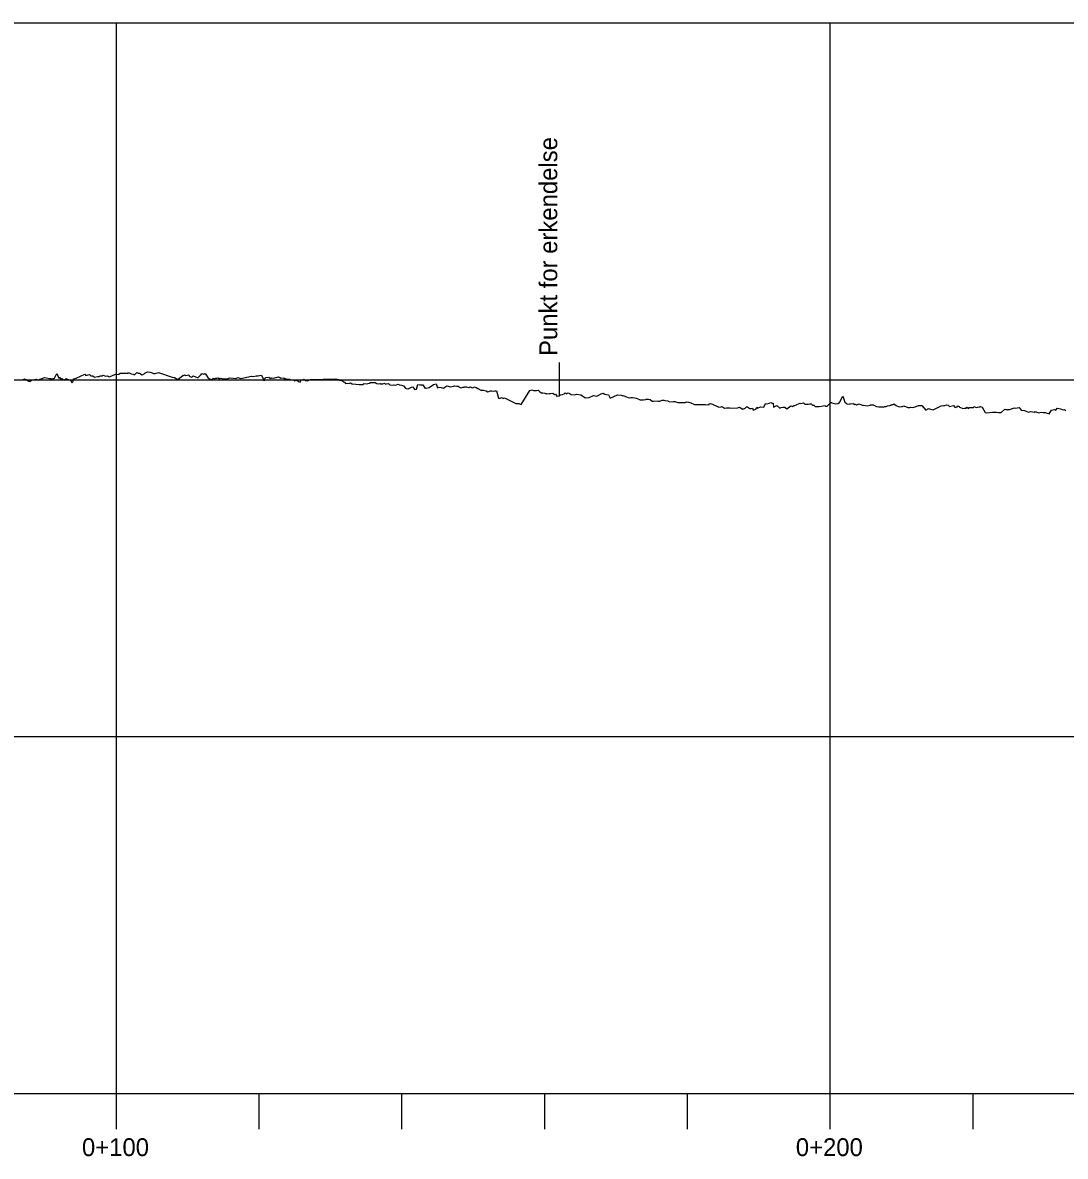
# Model space of a CAD drawing. Extents: x 0 to 513042, y 0 to 6212511.
# Drawn here: x 512219.9 to 512366, y 6211831.2 to 6211990 of the extents above; entities that cross this region are included whole.
import ezdxf

# ---------------------------------------------------------------- set-up
doc = ezdxf.new("R2010")
doc.units = 0
for name, color, linetype in [('TV_G_CL---', 7, 'Continuous'), ('TV_G_DTM_Exter', 7, 'Continuous'), ('TV_G_INF_SkrSg', 7, 'Continuous'), ('TV_L_---_Punkt', 7, 'Continuous'), ('TV_L_VER_Punkt', 7, 'Continuous')]:
    doc.layers.add(name, color=color, linetype=linetype)

msp = doc.modelspace()

# ---------------------------------------------------------------- linework, layer by layer
at = {"layer": 'TV_G_CL---'}
msp.add_line((511933.07, 6211840.01), (513033.07, 6211840.01), dxfattribs=at)
at = {"layer": 'TV_G_DTM_Exter'}
for p, q in [((512233.07, 6211835.01), (512233.07, 6211840.01)), ((512253.07, 6211835.01), (512253.07, 6211840.01)), ((512273.07, 6211835.01), (512273.07, 6211840.01)), ((512293.07, 6211835.01), (512293.07, 6211840.01)), ((512313.07, 6211835.01), (512313.07, 6211840.01)), ((512333.07, 6211835.01), (512333.07, 6211840.01)), ((512353.07, 6211835.01), (512353.07, 6211840.01))]:
    msp.add_line(p, q, dxfattribs=at)
at = {"layer": 'TV_G_INF_SkrSg'}
msp.add_lwpolyline([(512219.78, 6211940.01), (512220, 6211940.02), (512220.13, 6211940.08), (512220.22, 6211940.12), (512220.45, 6211940.04), (512220.81, 6211939.78), (512220.94, 6211939.75), (512221.17, 6211939.94), (512221.35, 6211940.01), (512221.85, 6211940.06), (512222.2, 6211939.95), (512222.34, 6211940.1), (512222.67, 6211940.16), (512223.01, 6211940.31), (512223.26, 6211940.25), (512223.72, 6211940.19), (512223.93, 6211940.19), (512224.11, 6211940.11), (512224.41, 6211940.23), (512224.75, 6211940.89), (512225.01, 6211940.23), (512225.17, 6211940.31), (512225.29, 6211940.09), (512225.46, 6211940.17), (512225.73, 6211939.96), (512225.98, 6211940.15), (512226.04, 6211940.18), (512226.1, 6211940.15), (512226.52, 6211939.98), (512226.67, 6211939.88), (512226.81, 6211939.58), (512227, 6211939.74), (512227.07, 6211940.13), (512227.46, 6211940.21), (512228.63, 6211940.77), (512228.81, 6211940.6), (512229.32, 6211940.73), (512229.5, 6211940.56), (512229.75, 6211940.57), (512230.01, 6211940.35), (512230.43, 6211940.45), (512230.67, 6211940.46), (512230.82, 6211940.53), (512231.1, 6211940.57), (512231.22, 6211940.62), (512231.43, 6211940.54), (512231.55, 6211940.5), (512231.82, 6211940.53), (512231.94, 6211940.5), (512232.08, 6211940.39), (512232.44, 6211940.55), (512232.61, 6211940.62), (512232.98, 6211940.76), (512233.15, 6211940.76), (512233.34, 6211940.75), (512233.4, 6211940.77), (512233.6, 6211940.94), (512234.09, 6211940.9), (512234.34, 6211940.93), (512234.5, 6211940.9), (512234.66, 6211940.89), (512234.75, 6211941.02), (512235.16, 6211940.84), (512235.42, 6211940.79), (512235.62, 6211940.71), (512235.94, 6211941.02), (512235.94, 6211941.02), (512236.14, 6211940.93), (512236.32, 6211940.92), (512236.68, 6211940.68), (512236.91, 6211940.78), (512237.06, 6211940.93), (512237.43, 6211941.09), (512237.81, 6211941.07), (512238.08, 6211940.95), (512238.27, 6211940.87), (512238.5, 6211940.88), (512238.99, 6211941.01), (512240.9, 6211940.36), (512241.21, 6211940.33), (512241.43, 6211940.18), (512241.66, 6211940.04), (512242.43, 6211940.62), (512242.49, 6211940.57), (512242.63, 6211940.7), (512242.8, 6211940.59), (512243.2, 6211940.69), (512243.25, 6211940.55), (512243.37, 6211940.44), (512243.62, 6211940.37), (512243.83, 6211940.54), (512244.38, 6211940.32), (512244.52, 6211940.3), (512244.95, 6211940.73), (512245.04, 6211940.86), (512245.34, 6211940.8), (512245.5, 6211940.86), (512245.89, 6211940.33), (512246.11, 6211940.12), (512246.47, 6211940), (512246.53, 6211940.12), (512246.61, 6211940.23), (512246.83, 6211940.13), (512247.02, 6211940.22), (512247.15, 6211940.23), (512247.3, 6211940.25), (512247.53, 6211940.12), (512247.59, 6211940.24), (512248.15, 6211940.11), (512248.72, 6211940.17), (512248.91, 6211940.25), (512249.42, 6211940.21), (512249.81, 6211940.18), (512250.07, 6211940.3), (512250.49, 6211940.19), (512251.98, 6211940.48), (512252.13, 6211940.45), (512252.47, 6211940.5), (512252.63, 6211940.57), (512252.95, 6211940.53), (512253.1, 6211940.59), (512253.4, 6211940.63), (512253.75, 6211939.87), (512253.94, 6211940.33), (512254.44, 6211940.36), (512254.63, 6211940.22), (512254.72, 6211940.18), (512254.81, 6211940.29), (512255.11, 6211940.24), (512255.61, 6211940.36), (512255.76, 6211940.43), (512255.88, 6211940.33), (512255.94, 6211940.35), (512256.11, 6211940.2), (512256.48, 6211940.27), (512256.61, 6211940.1), (512256.75, 6211940.16), (512256.9, 6211940.07), (512256.97, 6211940.1), (512257.11, 6211940.1), (512257.37, 6211940.09), (512257.51, 6211939.96), (512257.57, 6211939.99), (512257.88, 6211939.97), (512258, 6211939.84), (512258.05, 6211939.86), (512258.13, 6211939.9), (512258.36, 6211939.93), (512258.59, 6211939.74), (512258.81, 6211939.68), (512258.95, 6211939.93), (512259.09, 6211939.99), (512259.32, 6211940.09), (512259.57, 6211939.89), (512259.83, 6211939.85), (512260.02, 6211939.94), (512260.28, 6211940.05), (512263.83, 6211940.11), (512264.22, 6211940.04), (512264.45, 6211939.9), (512264.5, 6211939.92), (512264.79, 6211939.82), (512264.95, 6211939.71), (512265.01, 6211939.66), (512265.15, 6211939.49), (512265.39, 6211939.52), (512265.68, 6211939.48), (512265.73, 6211939.51), (512265.87, 6211939.57), (512266.12, 6211939.44), (512266.6, 6211939.37), (512267.09, 6211939.34), (512267.46, 6211939.33), (512267.64, 6211939.33), (512267.69, 6211939.43), (512267.72, 6211939.44), (512267.75, 6211939.46), (512268.08, 6211939.43), (512268.53, 6211939.53), (512268.69, 6211939.6), (512268.93, 6211939.62), (512269.32, 6211939.61), (512269.56, 6211939.46), (512269.83, 6211939.41), (512270.02, 6211939.49), (512270.08, 6211939.43), (512270.32, 6211939.45), (512270.41, 6211939.41), (512270.61, 6211939.5), (512270.77, 6211939.39), (512270.89, 6211939.44), (512271.2, 6211939.49), (512271.39, 6211939.3), (512271.89, 6211939.26), (512271.99, 6211939.31), (512272.23, 6211939.25), (512272.3, 6211939.28), (512272.54, 6211939.38), (512272.73, 6211939.29), (512273.03, 6211939.25), (512273.31, 6211939.13), (512273.55, 6211938.83), (512273.66, 6211938.78), (512273.93, 6211938.72), (512274.06, 6211938.78), (512274.43, 6211938.94), (512274.54, 6211938.99), (512274.86, 6211938.65), (512275.12, 6211938.68), (512275.29, 6211939.33), (512275.6, 6211939.28), (512275.98, 6211939.27), (512276.34, 6211938.78), (512276.39, 6211938.89), (512276.47, 6211938.84), (512276.87, 6211938.92), (512277.48, 6211939.35), (512277.88, 6211939.44), (512278.07, 6211938.87), (512278.24, 6211938.95), (512278.58, 6211938.93), (512278.89, 6211938.8), (512279.06, 6211938.94), (512279.34, 6211939.16), (512279.87, 6211939.03), (512280.07, 6211939.04), (512280.33, 6211939.08), (512280.5, 6211939.15), (512280.74, 6211939.09), (512280.97, 6211939.1), (512281.24, 6211938.9), (512281.36, 6211938.85), (512281.58, 6211938.95), (512281.8, 6211938.97), (512281.9, 6211939.01), (512282.1, 6211939.02), (512282.43, 6211938.93), (512282.59, 6211939), (512282.94, 6211938.88), (512283.24, 6211939.01), (512283.47, 6211938.93), (512283.69, 6211938.79), (512284.14, 6211938.54), (512284.49, 6211938.54), (512284.87, 6211938.44), (512285.11, 6211938.3), (512285.48, 6211938.47), (512285.68, 6211938.47), (512285.9, 6211938.41), (512286.1, 6211938.43), (512286.31, 6211938.44), (512286.6, 6211937.4), (512286.81, 6211937.41), (512287, 6211937.5), (512287.2, 6211937.42), (512287.27, 6211937.37), (512287.44, 6211937.45), (512289.03, 6211936.68), (512289.24, 6211936.67), (512289.47, 6211936.67), (512289.77, 6211936.54), (512291, 6211938.51), (512291.3, 6211938.57), (512291.48, 6211938.49), (512291.7, 6211938.5), (512291.9, 6211938.51), (512292.14, 6211938.54), (512292.39, 6211938.3), (512292.6, 6211938.16), (512292.83, 6211938.18), (512293.07, 6211938.1), (512293.27, 6211938.03), (512293.34, 6211938.06), (512293.71, 6211938.05), (512293.81, 6211938.09), (512293.82, 6211938.09), (512294.23, 6211938.12), (512294.44, 6211937.94), (512294.57, 6211937.99), (512294.76, 6211937.72), (512295.16, 6211937.73), (512295.3, 6211937.88), (512295.58, 6211937.92), (512295.82, 6211938.02), (512295.94, 6211938.15), (512296.07, 6211938.05), (512296.34, 6211938.17), (512296.63, 6211938.03), (512296.78, 6211937.94), (512297.28, 6211937.88), (512297.54, 6211937.99), (512298.12, 6211937.89), (512298.8, 6211937.47), (512299.31, 6211937.5), (512299.93, 6211937.78), (512300.36, 6211937.69), (512300.96, 6211938.01), (512301.25, 6211938.13), (512301.49, 6211937.97), (512301.67, 6211937.95), (512301.99, 6211937.91), (512302.23, 6211937.4), (512303.28, 6211937.89), (512303.79, 6211937.85), (512304, 6211937.76), (512304.06, 6211937.78), (512304.4, 6211937.66), (512304.91, 6211937.49), (512305.14, 6211937.5), (512305.33, 6211937.51), (512305.38, 6211937.52), (512305.63, 6211937.45), (512305.88, 6211937.4), (512306.36, 6211937.25), (512306.42, 6211937.19), (512306.92, 6211937.17), (512307.22, 6211937.22), (512307.3, 6211937.26), (512307.38, 6211937.29), (512307.62, 6211937.3), (512307.84, 6211937.22), (512308.11, 6211936.99), (512308.26, 6211936.98), (512308.31, 6211937), (512308.81, 6211937.05), (512309.03, 6211936.98), (512309.21, 6211936.98), (512309.55, 6211937.12), (512309.78, 6211937.13), (512309.89, 6211937.1), (512310.33, 6211937.04), (512310.39, 6211936.99), (512310.61, 6211936.91), (512311.08, 6211936.95), (512311.3, 6211936.96), (512311.71, 6211936.79), (512311.99, 6211936.83), (512312.11, 6211936.81), (512312.52, 6211936.81), (512312.76, 6211936.83), (512312.86, 6211936.88), (512312.94, 6211936.91), (512313.21, 6211936.85), (512313.53, 6211936.75), (512313.95, 6211936.59), (512314.04, 6211936.54), (512314.4, 6211936.53), (512314.76, 6211936.53), (512315.2, 6211936.54), (512315.37, 6211936.53), (512315.6, 6211936.55), (512316.06, 6211936.49), (512316.16, 6211936.62), (512316.3, 6211936.68), (512316.6, 6211936.57), (512317.47, 6211936.16), (512317.79, 6211936.22), (512317.86, 6211936.25), (512317.99, 6211936.22), (512318.24, 6211936), (512318.52, 6211936.05), (512318.67, 6211936.06), (512319, 6211936.08), (512319.39, 6211936.01), (512320.09, 6211936.05), (512320.36, 6211936.16), (512320.83, 6211935.89), (512321.17, 6211936.04), (512321.41, 6211936.23), (512321.81, 6211935.96), (512322.01, 6211935.97), (512322.16, 6211936.03), (512322.28, 6211935.76), (512322.7, 6211935.94), (512322.81, 6211936.14), (512322.88, 6211936.02), (512323.31, 6211936.2), (512323.78, 6211936.16), (512323.99, 6211936.67), (512324.29, 6211936.63), (512324.76, 6211936.83), (512324.93, 6211936.72), (512325.06, 6211936.7), (512325.14, 6211936.17), (512325.61, 6211936.37), (512326.03, 6211936.04), (512326.22, 6211936.12), (512326.48, 6211936.15), (512326.69, 6211936.15), (512327, 6211935.92), (512327.57, 6211936.33), (512327.82, 6211936.26), (512327.98, 6211936.41), (512328.13, 6211936.39), (512328.33, 6211936.48), (512328.41, 6211936.51), (512328.86, 6211936.71), (512328.96, 6211936.67), (512329.34, 6211936.76), (512329.52, 6211936.57), (512329.99, 6211936.6), (512330.23, 6211936.62), (512330.39, 6211936.61), (512330.46, 6211936.56), (512330.59, 6211936.46), (512330.78, 6211936.46), (512330.96, 6211936.27), (512331.52, 6211936.25), (512332.07, 6211936.34), (512332.34, 6211936.37), (512332.43, 6211936.32), (512332.62, 6211936.32), (512333.17, 6211936.83), (512333.27, 6211936.79), (512333.29, 6211936.78), (512333.85, 6211936.64), (512334.15, 6211936.68), (512334.39, 6211936.79), (512334.83, 6211937.69), (512335.1, 6211936.84), (512335.26, 6211936.75), (512335.38, 6211936.62), (512335.52, 6211936.6), (512335.77, 6211936.63), (512335.93, 6211936.62), (512336.27, 6211936.68), (512336.52, 6211936.52), (512336.59, 6211936.56), (512336.77, 6211936.47), (512337.12, 6211936.63), (512337.55, 6211936.46), (512337.69, 6211936.44), (512338, 6211936.4), (512338.24, 6211936.35), (512338.65, 6211936.44), (512338.71, 6211936.47), (512339.12, 6211936.47), (512339.2, 6211936.42), (512339.37, 6211936.33), (512339.53, 6211936.24), (512339.89, 6211936.22), (512340.05, 6211936.21), (512340.4, 6211936.2), (512340.47, 6211936.15), (512340.68, 6211936.24), (512340.92, 6211936.26), (512341.09, 6211936.33), (512341.42, 6211936.4), (512341.49, 6211936.43), (512341.55, 6211936.45), (512341.7, 6211936.52), (512341.84, 6211936.5), (512341.97, 6211936.64), (512342.31, 6211936.38), (512342.74, 6211936.22), (512343.07, 6211936.27), (512343.2, 6211936.25), (512343.39, 6211936.34), (512343.93, 6211936.13), (512344.23, 6211936.1), (512344.32, 6211936.14), (512344.62, 6211936.11), (512345.11, 6211936.23), (512345.44, 6211936.38), (512345.52, 6211936.41), (512345.88, 6211936.4), (512346.48, 6211935.72), (512346.79, 6211935.94), (512346.8, 6211935.95), (512347.47, 6211935.8), (512347.97, 6211936.04), (512348.6, 6211936.35), (512348.94, 6211936.41), (512349.11, 6211936.4), (512349.34, 6211936.5), (512349.6, 6211936.44), (512349.78, 6211936.25), (512350.32, 6211936.4), (512350.58, 6211936.11), (512350.84, 6211936.22), (512350.93, 6211936.35), (512351.11, 6211936.27), (512351.2, 6211936.14), (512351.68, 6211935.99), (512351.9, 6211936), (512352.09, 6211936.01), (512352.22, 6211936.14), (512352.43, 6211935.99), (512352.53, 6211936.12), (512352.97, 6211936.13), (512353.14, 6211936.13), (512353.19, 6211936.24), (512353.43, 6211936.17), (512353.52, 6211936.12), (512353.91, 6211936.22), (512354.07, 6211936.2), (512354.12, 6211936.23), (512354.37, 6211936.17), (512354.77, 6211935.39), (512355.01, 6211935.35), (512355.78, 6211935.44), (512356.01, 6211935.46), (512356.38, 6211935.46), (512356.66, 6211935.4), (512357.03, 6211935.4), (512357.51, 6211935.86), (512357.65, 6211935.84), (512358.17, 6211935.82), (512358.9, 6211936.08), (512358.98, 6211936.03), (512359.25, 6211936.07), (512359.53, 6211936.11), (512359.84, 6211935.75), (512360.29, 6211935.7), (512360.83, 6211935.44), (512361.19, 6211935.54), (512361.62, 6211935.48), (512361.66, 6211935.49), (512361.9, 6211935.52), (512362.25, 6211935.37), (512362.6, 6211935.47), (512362.89, 6211935.43), (512363.16, 6211935.4), (512363.42, 6211935.34), (512363.65, 6211935.29), (512363.75, 6211935.24), (512364.06, 6211935.74), (512364.43, 6211935.82), (512364.66, 6211935.76), (512364.86, 6211936.03), (512365.35, 6211935.93), (512365.68, 6211935.8), (512365.91, 6211935.81), (512366.06, 6211935.64)], dxfattribs=at)
at = {"layer": 'TV_L_---_Punkt'}
msp.add_line((512295.16, 6211937.73), (512295.16, 6211942.42), dxfattribs=at)
at = {"layer": 'TV_L_VER_Punkt'}
for p, q in [((511933.07, 6211990.01), (513033.07, 6211990.01)), ((511933.07, 6211990.01), (513033.07, 6211990.01)), ((512233.07, 6211840.01), (512233.07, 6211990.01)), ((512333.07, 6211840.01), (512333.07, 6211990.01)), ((511933.07, 6211940.01), (513033.07, 6211940.01)), ((511933.07, 6211890.01), (513033.07, 6211890.01))]:
    msp.add_line(p, q, dxfattribs=at)

# ---------------------------------------------------------------- texts
msp.add_text('Punkt for erkendelse', height=2.5, rotation=90).set_placement((512294.83, 6211943.33))
for s, p in [('0+100', (512228.25, 6211831.26)), ('0+200', (512328.25, 6211831.26))]:
    msp.add_text(s, height=2.5).set_placement(p)

doc.saveas('drawing.dxf')
